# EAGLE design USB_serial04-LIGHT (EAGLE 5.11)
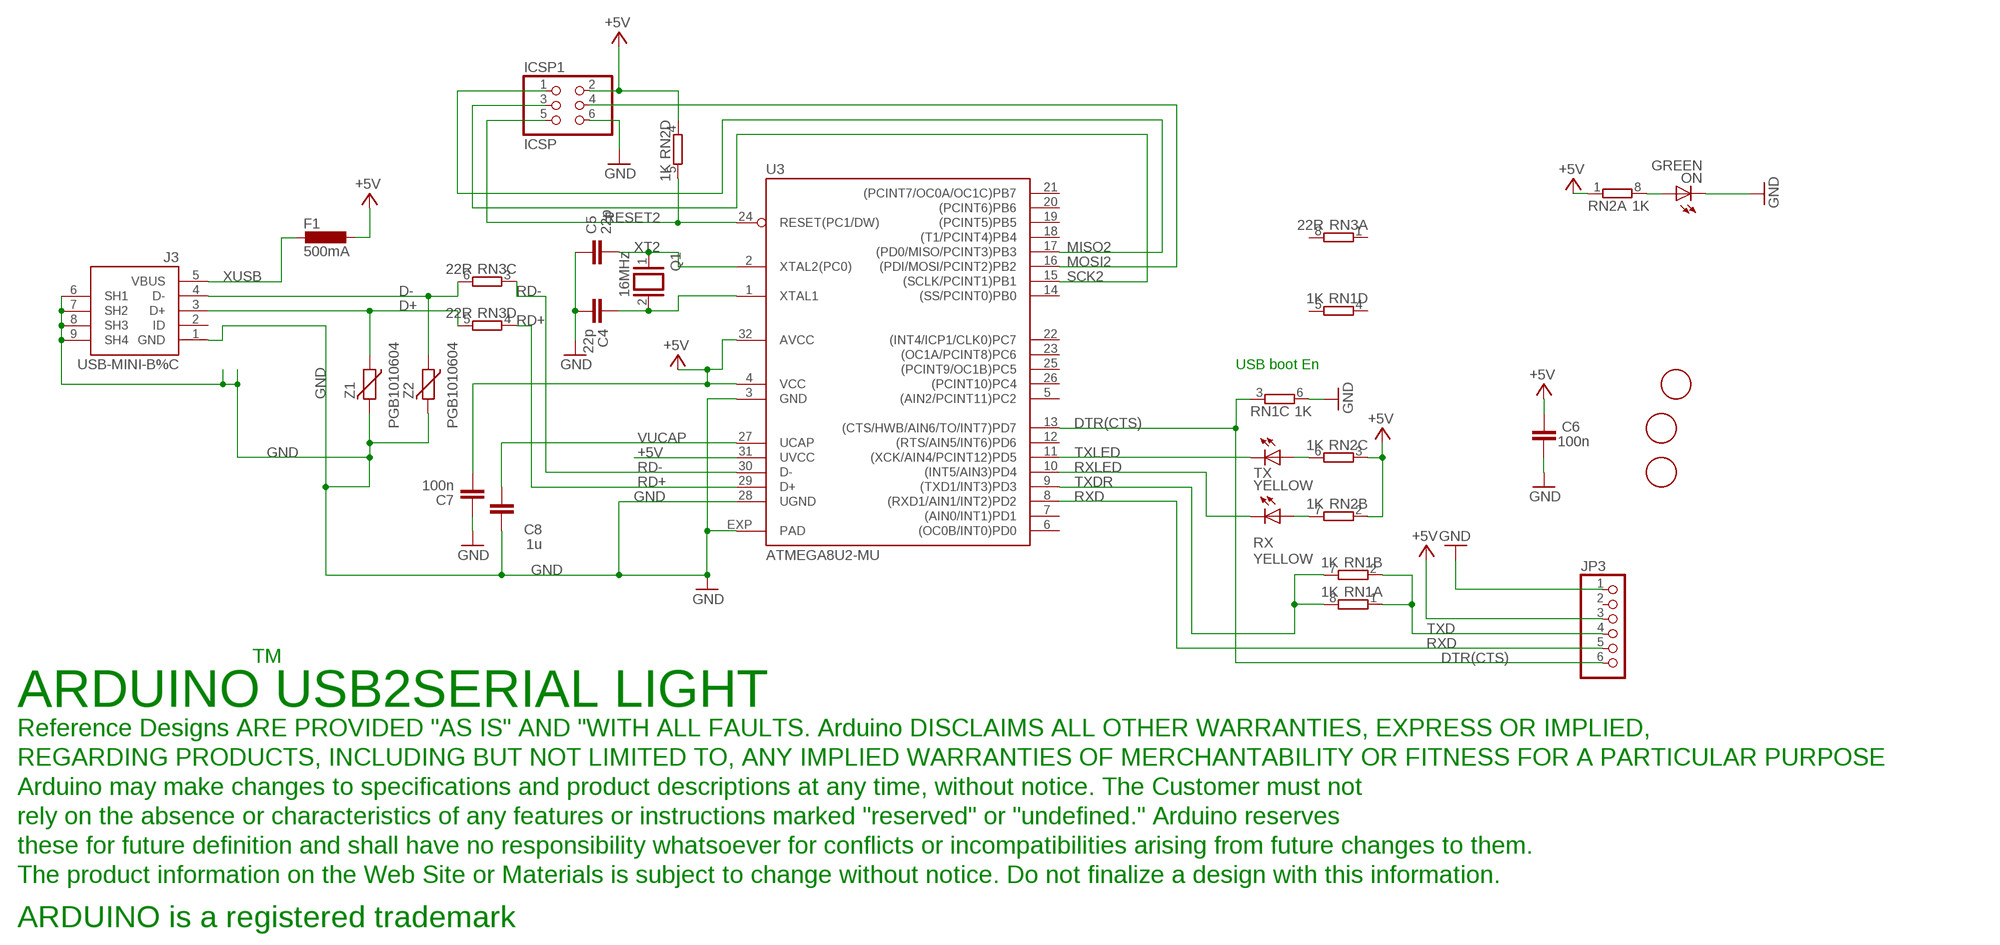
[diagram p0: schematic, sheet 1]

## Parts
C4  22p  C-EU0603-RND  [C0603-ROUND]
C5  22p  C-EU0603-RND  [C0603-ROUND]
C6  100n  C-EU0603-RND  [C0603-ROUND]
C7  100n  C-EU0603-RND  [C0603-ROUND]
C8  1u  C-EU0603-RND  [C0603-ROUND]
F1  500mA  L-EUL1812  [L1812]
ICSP1  ICSP  PINHD-2X3  [2X03]
J3  USB-MINI-B%C  [USB-MINI-B_2]
JP3  PINHD-1X6LITTLE  [1X06_LITTLE]
ON  GREEN  LEDCHIP-LED0805  [CHIP-LED0805]
Q1  16MHz  XTAL/S  [QS]
RN1  1K  4R-NCAY16  [CAY16]
RN2  1K  4R-NCAY16  [CAY16]
RN3  22R  4R-NCAY16  [CAY16]
RX  YELLOW  LEDCHIP-LED0805  [CHIP-LED0805]
TX  YELLOW  LEDCHIP-LED0805  [CHIP-LED0805]
U3  ATMEGA8U2-MU  [QFN32]
U$3  FIDUCIALMOUNT  [FIDUCIA-MOUNT]
U$4  FIDUCIALMOUNT  [FIDUCIA-MOUNT]
U$6  FIDUCIALMOUNT  [FIDUCIA-MOUNT]
Z1  PGB1010604  VARISTORCN0603  [CT/CN0603]
Z2  PGB1010604  VARISTORCN0603  [CT/CN0603]

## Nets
+5V [usbvcc]: C6.2 C7.1 F1.1 ICSP1.2 JP3.3 RN2.1 RN2.2 RN2.3 RN2.4 U3.4(VCC) U3.31(UVCC) U3.32(AVCC)
D+: J3.3(D+) RN3.5 Z1.1
D-: J3.4(D-) RN3.6 Z2.1
DTR(CTS): JP3.6 RN1.3 U3.13((CTS/HWB/AIN6/TO/INT7)PD7)
GND [gnd]: C4.1 C5.2 C6.1 C7.2 C8.2 ICSP1.6 J3.1(GND) J3.6(SH1) J3.7(SH2) J3.8(SH3) J3.9(SH4) JP3.1 ON.C RN1.6 U3.3(GND) U3.28(UGND) U3.EXP(PAD) Z1.2 Z2.2
MISO2: ICSP1.1 U3.17((PD0/MISO/PCINT3)PB3)
MOSI2: ICSP1.4 U3.16((PDI/MOSI/PCINT2)PB2)
N$1: C4.2 Q1.2 U3.1(XTAL1)
N$2: ON.A RN2.8
N$35: RN2.7 RX.A
N$36: RN2.6 TX.A
RD+: RN3.4 U3.29(D+)
RD-: RN3.3 U3.30(D-)
RESET2: ICSP1.5 RN2.5 U3.24(RESET(PC1/DW))
RXD: JP3.5 U3.8((RXD1/AIN1/INT2)PD2)
RXLED: RX.C U3.10((INT5/AIN3)PD4)
SCK2: ICSP1.3 U3.15((SCLK/PCINT1)PB1)
TXD: JP3.4 RN1.1 RN1.2
TXDR: RN1.7 RN1.8 U3.9((TXD1/INT3)PD3)
TXLED: TX.C U3.11((XCK/AIN4/PCINT12)PD5)
VUCAP: C8.1 U3.27(UCAP)
XT2: C5.1 Q1.1 U3.2(XTAL2(PC0))
XUSB [usbvcc]: F1.2 J3.5(VBUS)
Unconnected: J3.2(ID) JP3.2 RN1.4 RN1.5 RN3.1 RN3.2 RN3.7 RN3.8 U3.5((AIN2/PCINT11)PC2) U3.6((OC0B/INT0)PD0) U3.7((AIN0/INT1)PD1) U3.12((RTS/AIN5/INT6)PD6) U3.14((SS/PCINT0)PB0) U3.18((T1/PCINT4)PB4) U3.19((PCINT5)PB5) U3.20((PCINT6)PB6) U3.21((PCINT7/OC0A/OC1C)PB7) U3.22((INT4/ICP1/CLK0)PC7) U3.23((OC1A/PCINT8)PC6) U3.25((PCINT9/OC1B)PC5) U3.26((PCINT10)PC4)

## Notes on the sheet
- USB boot En
- TM
- ARDUINO USB2SERIAL LIGHT
- Reference Designs ARE PROVIDED "AS IS" AND "WITH ALL FAULTS. Arduino DISCLAIMS ALL OTHER WARRANTIES, EXPRESS OR IMPLIED,
- REGARDING PRODUCTS, INCLUDING BUT NOT LIMITED TO, ANY IMPLIED WARRANTIES OF MERCHANTABILITY OR FITNESS FOR A PARTICULAR PURPOSE
- Arduino may make changes to specifications and product descriptions at any time, without notice. The Customer must not
- rely on the absence or characteristics of any features or instructions marked "reserved" or "undefined." Arduino reserves
- these for future definition and shall have no responsibility whatsoever for conflicts or incompatibilities arising from future changes to them.
- The product information on the Web Site or Materials is subject to change without notice. Do not finalize a design with this information.
- ARDUINO is a registered trademark

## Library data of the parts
C4-C8 = SmartPrj:C-EU: CAPACITOR, European symbol
F1 = rcl:L-EU: INDUCTOR, European symbol
ICSP1 = pinhead:PINHD-2X3: PIN HEADER
J3 = MyCON2:USB-MINI-B
JP3 = SmartPrj:PINHD-1X6: PIN HEADER
ON RX TX = led:LED: LED
Q1 = special:XTAL/S: CRYSTAL
RN1-RN3 = resistor-dil:4R-N: Array Chip Resistor Source: RS Component / Phycomp
U3 = atmel:ATMEGA8U2-MU
U$3 U$4 U$6 = SmartPrj:FIDUCIALMOUNT
Z1 Z2 = varistor:VARISTOR: VARISTOR

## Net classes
0 default: width 0.254 mm, clearance 0.254 mm
1 power: width 0.61 mm, clearance 0.254 mm
2 gnd: width 0.305 mm, drill 0.559 mm, clearance 0.254 mm
3 usbvcc: width 0.356 mm, clearance 0.254 mm
4 aref: width 0.406 mm, drill 0.61 mm, clearance 0.254 mm

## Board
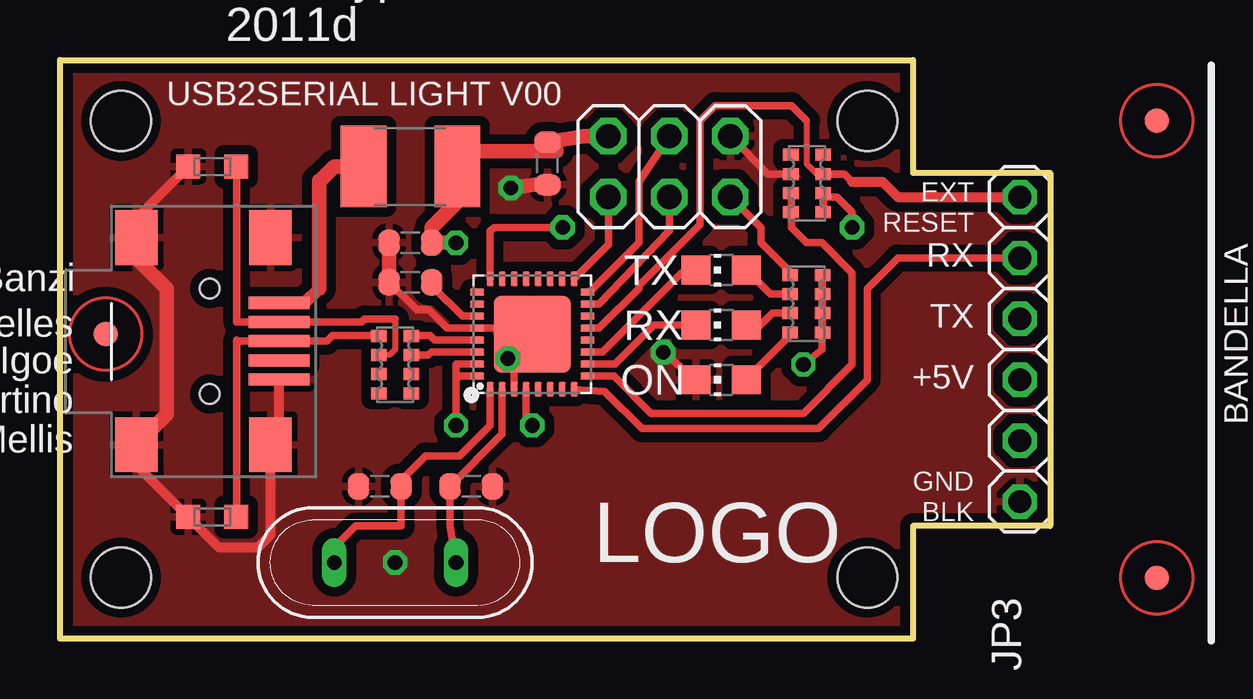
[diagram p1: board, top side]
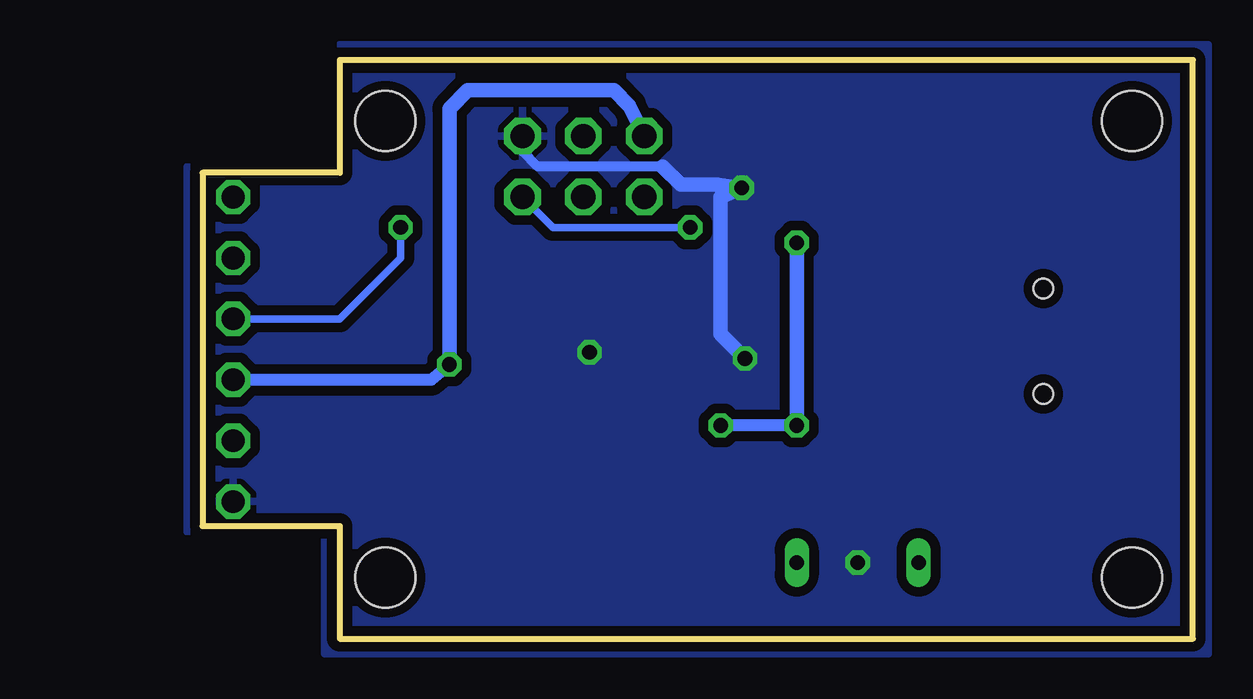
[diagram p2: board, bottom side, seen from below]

Size 41.27 x 24.13 mm. Coordinates in mm from the lower left corner, seen from the top.
Outline: 0,0 0,24.13 35.56,24.13 35.56,19.43 41.27,19.43 41.27,4.7 35.56,4.7 35.56,0 0,0
Copper layers (1*16): Top 0.035mm / dielectric 1.5mm / Bottom 0.035mm
Design rules "ArduinoDEF": minimum track width 6mil, minimum drill 12mil, track to track 5mil, track to pad 5mil, pad to pad 5mil, via to via 5mil, smd to smd 4mil, copper to edge 10mil, drill to drill 6mil, minimum pad ring 8mil, minimum via ring 8mil, stop-mask expansion 0mil, vias tented up to drill 0mil, thermal gap 10mil
Holes 2.5 mm at 2.54,21.59 2.54,2.54 33.66,2.54 33.66,21.59

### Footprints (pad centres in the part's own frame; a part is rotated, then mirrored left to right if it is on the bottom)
C0603-ROUND = smd 0.898 x 1.1: 1 -0.889,0; 2 0.889,0
L1812 = smd 1.9 x 3.4: 1 -1.95,0; 2 1.95,0
2X03 = drill 1.016 octagon: 1 -2.54,-1.27; 2 -2.54,1.27; 3 0,-1.27; 4 0,1.27; 5 2.54,-1.27; 6 2.54,1.27
USB-MINI-B_2 = smd 0.508 x 2.54: 1 0,0; 2 0.8,0; 3 1.6,0; 4 2.4,0; 5 3.2,0 | smd 2.286 x 1.778: 6 -2.717,5.948; 7 -2.717,0.36; 8 5.918,0.36; 9 5.918,5.948 | hole 0.813: -0.6,2.9; 3.8,2.9
1X06_LITTLE = drill 0.95 pad 1.422 octagon: 1 -6.35,0; 2 -3.81,0; 3 -1.27,0; 4 1.27,0; 5 3.81,0; 6 6.35,0
CHIP-LED0805 = smd 1.2 x 1.2: A 0,-1.05; C 0,1.05
QS = drill 0.61 long: 1 -2.54,0; 2 2.54,0
CAY16 = smd 0.5 x 0.65: 1 -1.2,-0.675; 2 -0.4,-0.675; 3 0.4,-0.675; 4 1.2,-0.675; 5 1.2,0.675; 6 0.4,0.675; 7 -0.4,0.675; 8 -1.2,0.675
QFN32 = smd 0.6 x 0.3: 1 -2.3,1.75; 2 -2.3,1.25; 3 -2.3,0.75; 4 -2.3,0.25; 5 -2.3,-0.25; 6 -2.3,-0.75; 7 -2.3,-1.25; 8 -2.3,-1.75; 17 2.3,-1.75; 18 2.3,-1.25; 19 2.3,-0.75; 20 2.3,-0.25; 21 2.3,0.25; 22 2.3,0.75; 23 2.3,1.25; 24 2.3,1.75 | smd 0.3 x 0.6: 9 -1.75,-2.3; 10 -1.25,-2.3; 11 -0.75,-2.3; 12 -0.25,-2.3; 13 0.25,-2.3; 14 0.75,-2.3; 15 1.25,-2.3; 16 1.75,-2.3; 25 1.75,2.3; 26 1.25,2.3; 27 0.75,2.3; 28 0.25,2.3; 29 -0.25,2.3; 30 -0.75,2.3; 31 -1.25,2.3; 32 -1.75,2.3 | smd 3.2 x 3.2: EXP 0,0
FIDUCIA-MOUNT@1 = smd 1.016 x 1.016: P$1 0,0
CT/CN0603 = smd 1 x 1: 1 -1,0; 2 1,0

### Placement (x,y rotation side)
C4  13.34,6.35 0 top
C5  17.14,6.35 0 top
C6  20.32,19.81 90 top
C7  14.61,16.51 180 top
C8  14.61,14.86 180 top
F1  14.61,19.68 180 top
ICSP1  25.4,19.68 0 top
J3  9.13,10.8 90 top
JP3  40.01,12.06 90 top
ON  27.56,10.79 90 top
Q1  13.97,3.17 180 top
RN1  31.14,18.98 90 top
RN2  31.11,13.97 90 top
RN3  13.97,11.43 90 top
RX  27.56,13.08 90 top
TX  27.56,15.37 90 top
U3  19.68,12.7 90 top
U$3  FIDUCIALMOUNT  [FIDUCIA-MOUNT@1]  1.91,12.7 0 top
U$4  FIDUCIALMOUNT  [FIDUCIA-MOUNT@1]  not placed on the board
U$6  FIDUCIALMOUNT  [FIDUCIA-MOUNT@1]  not placed on the board
Z1  6.35,5.08 180 top
Z2  6.35,19.68 180 top

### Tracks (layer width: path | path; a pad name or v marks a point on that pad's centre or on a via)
+5V  (via drill 0.61)
  Top 0.305: RN2.1 RN2.2 RN2.3 RN2.4 31.75,15.21 31.75,12.06 v30.99,11.43 | v16.51,8.89 16.51,10.79 | 16.51,10.79 16.51,11.43 16.53,11.45 U3.31 | U3.32 16.66,10.95 16.51,10.79 | U3.4 19.43,9.14 v19.68,8.89
  Top 0.61: ICSP1.2 21.84,20.95 C6.2 20.7,20.32 17.14,20.32 F1.1 16.55,18.21 15.49,17.14 C7.1 v16.51,16.51
  Bottom 0.508: v16.51,8.89 v19.68,8.89 | v30.99,11.43 31.75,10.79 JP3.3
  Bottom 0.61: ICSP1.2 23.5,22.23 24.13,22.86 30.23,22.86 30.99,22.1 v30.99,11.43 | v16.51,8.89 v16.51,16.51
D+
  Top 0.305: RN3.5 11.36,12.63 11.13,12.4 J3.3 7.41,12.4 7.37,12.45 7.37,5.1 Z1.1
D-
  Top 0.254: 13.97,13.34 13.97,12.06 13.73,11.83 RN3.6
  Top 0.305: 13.97,13.34 12.7,13.34 12.57,13.21 J3.4 7.37,13.21 7.37,19.67 Z2.1
DTR(CTS)
  Top 0.254: RN1.3 31.55,19.38 31.11,19.81 31.11,21.59
  Top 0.305: U3.13 22.48,12.95 24.13,14.61 24.13,14.73 26.67,17.27 26.67,21.59 27.3,22.23 30.48,22.23 31.11,21.59 | 33.02,19.05 32.69,19.38 RN1.3
  Top 0.406: 33.02,19.05 34.29,19.05 34.92,18.41 JP3.6
GND  (via drill 0.61)
  Top 0.305: v25.15,11.94 ON.C | U3.3 18.93,11.95 U3.EXP 19.43,12.95 U3.28 16.13,12.95 15.37,13.72 14.86,13.72 C8.2 | RN1.6 29.52,19.38 ICSP1.6
  Top 0.406: J3.1 9.13,8.45 J3.7 8.78,4.33 8.26,3.81 6.62,3.81 Z1.2 3.19,7.24 J3.6 | 3.19,17.52 Z2.2
  Top 0.61: C6.1 19.81,18.92 v18.8,18.8 | C8.2 C7.2 | J3.6 4.45,9.35 4.45,14.61 3.19,15.86 J3.9 3.19,17.52
  Bottom 0.406: 22.1,19.68 27.3,19.68 27.94,20.32 ICSP1.6
  Bottom 0.61: v18.67,11.68 U3.EXP 19.68,18.41 v18.8,18.8 19.81,18.92 21.34,18.92 22.1,19.68
  other vias: 13.97,3.17
  pour Top (isolate 0.406): 0,24.13 35.56,24.13 35.56,19.68 41.27,19.68 41.27,4.45 35.56,4.45 35.56,0 0,0
  pour Bottom (isolate 0.406): -0.64,24.77 35.56,24.77 35.56,19.68 41.91,19.68 41.91,4.45 36.2,4.45 36.2,-0.64 -0.64,-0.64
MISO2
  Top 0.305: ICSP1.1 22.86,16.43 U3.17
MOSI2
  Top 0.305: U3.16 22.07,14.45 24.13,16.51 24.13,19.05 ICSP1.4
N$1
  Top 0.305: U3.1 17.93,8.89 16.66,7.62 15.24,7.62 14.22,6.6 C4.2 14.22,4.7 12.32,4.7 11.43,3.81 Q1.2
N$2
  Top 0.305: RN2.8 30.44,12.66 28.57,10.79 ON.A
N$35
  Top 0.305: RX.A 28.83,12.7 29.7,13.57 RN2.7
N$36
  Top 0.305: RN2.6 29.61,14.37 TX.A
RD+
  Top 0.305: U3.29 15.62,12.45 15.44,12.63 RN3.4
RD-
  Top 0.305: U3.30 15.48,11.95 15.35,11.83 RN3.3
RESET2  (via drill 0.61)
  Top 0.305: RN2.5 30.44,15.28 29.21,16.51 29.21,17.14 ICSP1.5 | U3.24 17.93,16.99 18.09,17.14 v20.95,17.14
  Bottom 0.305: v20.95,17.14 26.67,17.14 ICSP1.5
RXD
  Top 0.305: U3.8 22.7,10.31 24.26,8.76 31.62,8.76 33.66,10.79 33.66,14.61 34.92,15.88 JP3.5
RXLED
  Top 0.305: U3.10 23.13,11.45 24.77,13.08 RX.C
SCK2
  Top 0.305: U3.15 22.46,13.95 25.4,17.02 ICSP1.3
TXD  (via drill 0.61)
  Top 0.305: v33.02,17.14 33.02,17.78 32.38,18.41 31.98,18.41 RN1.2 RN1.1
  Bottom 0.305: JP3.4 35.56,13.34 33.02,15.88 v33.02,17.14
TXDR
  Top 0.305: U3.9 23.09,10.95 24.64,9.4 30.99,9.4 33.02,11.43 33.02,15.24 31.75,16.51 31.11,16.51 30.48,17.14 RN1.8 | RN1.8 RN1.7 | RN1.8
TXLED
  Top 0.305: U3.11 22.62,11.95 25.91,15.24 TX.C
VUCAP
  Top 0.305: U3.27 16.78,13.45 15.62,14.61 15.62,14.73 C8.1
XT2
  Top 0.305: U3.2 18.43,8.53 C5.1 16.26,4.7 Q1.1
XUSB
  Top 0.508: J3.5 10.2,14.01 10.79,14.61
  Top 0.61: 10.79,14.61 10.79,19.09 10.84,19.09 11.43,19.68 F1.2

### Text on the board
Top: ARDUINO USB2SERIAL LIGHT | Reference Designs ARE PROVIDED "AS IS" AND "WITH ALL FAULTS. Arduino DISCLAIMS ALL OTHER WARRANTIES, EXPRESS OR IMPLIED, | REGARDING PRODUCTS, INCLUDING BUT NOT LIMITED TO, ANY IMPLIED WARRANTIES OF MERCHANTABILITY OR FITNESS FOR A PARTICULAR PURPOSE | Arduino may make changes to specifications and product descriptions at any time, without notice. The Customer must not | rely on the absence or characteristics of any features or instructions marked "reserved" or "undefined." Arduino reserves | these for future definition and shall have no responsibility whatsoever for conflicts or incompatibilities arising from future changes to them. | The product information on the Web Site or Materials is subject to change without notice. Do not finalize a design with this information. | ARDUINO is a registered trademark
tPlace: Prototype | Limited | Edition | 2011d | USB2SERIAL LIGHT V00 | EXT | RESET | RX | TX | TX | RX | +5V | BANDELLA | GND | BLK | LOGO
tNames: TM | Arduino | M.Banzi | D.Cuartielles | T.Igoe | G.Martino | D.Mellis
214bmp: D:/SmartProjects/Snc/a4_bn_logo2.bmp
